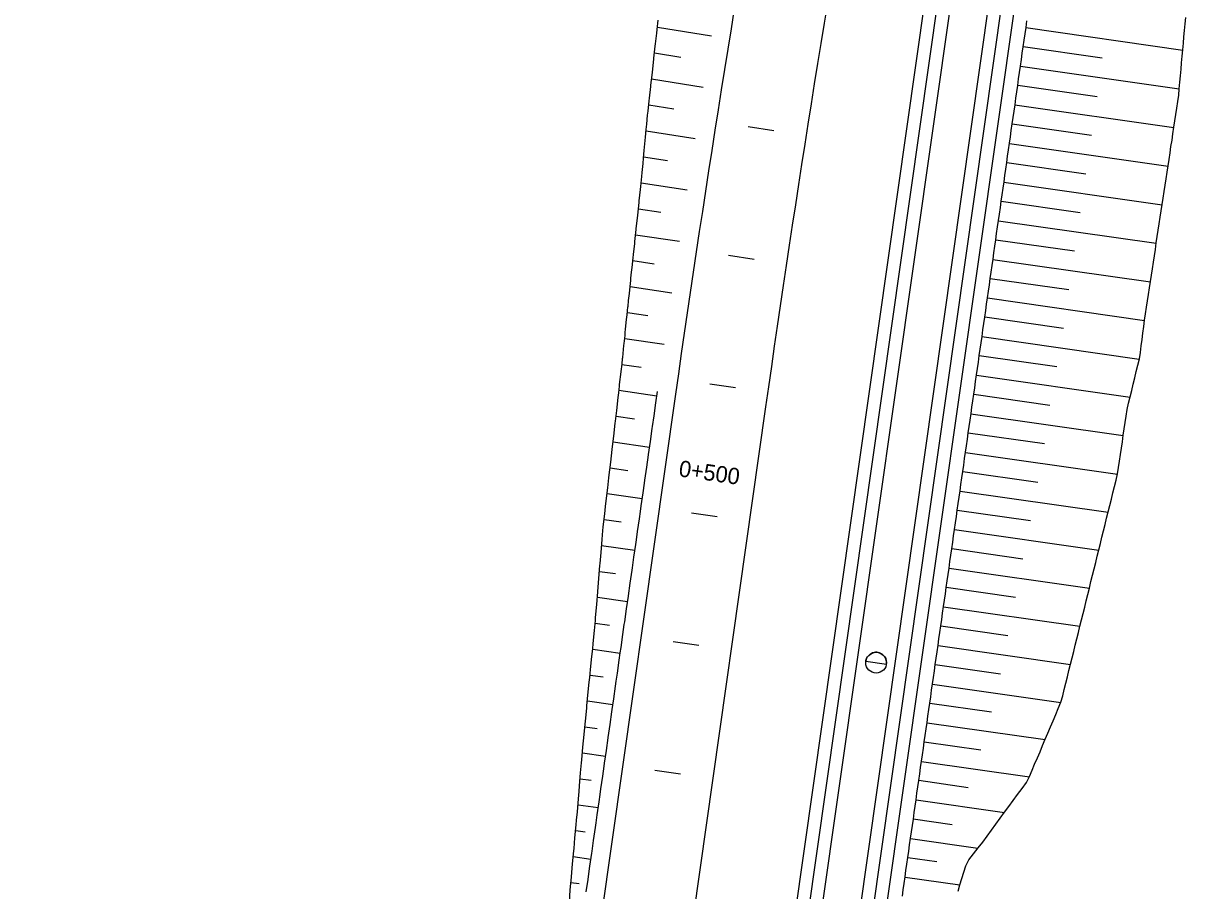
# Model space of a CAD drawing. Extents: x 6503541 to 6503743, y 5888004 to 5888145.
# Drawn here: x 6503703.334 to 6503705.481, y 5888126.143 to 5888127.745 of the extents above; entities that cross this region are included whole.
import ezdxf

# ---------------------------------------------------------------- set-up
doc = ezdxf.new("R2010")
doc.units = 0
doc.layers.add('12', color=7, linetype='Continuous')

msp = doc.modelspace()

# ---------------------------------------------------------------- linework, layer by layer
at = {"layer": '12'}
for p, q in [((6503703.334, 5888115.918), (6503705.1445, 5888128.6327)), ((6503703.8373, 5888119.6233), (6503705.1208, 5888128.6361)), ((6503703.3577, 5888115.9146), (6503705.1683, 5888128.6294)), ((6503703.4266, 5888115.9048), (6503705.2372, 5888128.6195)), ((6503703.4504, 5888115.9014), (6503705.2609, 5888128.6162)), ((6503704.0013, 5888119.5999), (6503705.2847, 5888128.6128)), ((6503705.1861, 5888127.7365), (6503705.4758, 5888127.6952)), ((6503705.3268, 5888127.6801), (6503705.181, 5888127.7008)), ((6503705.1759, 5888127.6652), (6503705.4693, 5888127.6234)), ((6503705.3178, 5888127.6086), (6503705.1709, 5888127.6295)), ((6503705.1658, 5888127.5939), (6503705.4594, 5888127.5521)), ((6503705.3073, 5888127.5374), (6503705.1607, 5888127.5582)), ((6503705.1556, 5888127.5226), (6503705.4486, 5888127.4809)), ((6503705.2969, 5888127.4661), (6503705.1506, 5888127.487)), ((6503705.1455, 5888127.4513), (6503705.4377, 5888127.4097)), ((6503705.2864, 5888127.3949), (6503705.1404, 5888127.4157)), ((6503705.1353, 5888127.38), (6503705.4269, 5888127.3385)), ((6503705.2759, 5888127.3237), (6503705.1303, 5888127.3444)), ((6503705.1252, 5888127.3088), (6503705.416, 5888127.2673)), ((6503705.2654, 5888127.2524), (6503705.1201, 5888127.2731)), ((6503705.115, 5888127.2375), (6503705.4053, 5888127.1962)), ((6503705.2553, 5888127.1811), (6503705.11, 5888127.2018)), ((6503705.1049, 5888127.1662), (6503705.3955, 5888127.1248)), ((6503705.2434, 5888127.1101), (6503705.0998, 5888127.1306)), ((6503705.0947, 5888127.0949), (6503705.3784, 5888127.0545)), ((6503704.5387, 5888127.06), (6503703.8027, 5888121.8909)), ((6503705.2304, 5888127.0392), (6503705.0897, 5888127.0593)), ((6503704.7051, 5888127.0363), (6503703.969, 5888121.8672)), ((6503705.0846, 5888127.0236), (6503705.3659, 5888126.9836)), ((6503705.2201, 5888126.968), (6503705.0795, 5888126.988)), ((6503705.0744, 5888126.9524), (6503705.3553, 5888126.9124)), ((6503705.208, 5888126.897), (6503705.0694, 5888126.9167)), ((6503705.0643, 5888126.8811), (6503705.338, 5888126.8421)), ((6503705.1943, 5888126.8262), (6503705.0592, 5888126.8454)), ((6503705.0541, 5888126.8098), (6503705.3206, 5888126.7719)), ((6503705.1805, 5888126.7554), (6503705.0491, 5888126.7742)), ((6503705.044, 5888126.7385), (6503705.3032, 5888126.7016)), ((6503705.1667, 5888126.6847), (6503705.0389, 5888126.7029)), ((6503705.0338, 5888126.6672), (6503705.2858, 5888126.6314)), ((6503705.1529, 5888126.6139), (6503705.0288, 5888126.6316)), ((6503705.0237, 5888126.596), (6503705.2684, 5888126.5611)), ((6503705.1391, 5888126.5432), (6503705.0186, 5888126.5603)), ((6503705.0135, 5888126.5247), (6503705.2506, 5888126.4909)), ((6503705.1223, 5888126.4728), (6503705.0085, 5888126.489)), ((6503705.0034, 5888126.4534), (6503705.2216, 5888126.4223)), ((6503705.1027, 5888126.4029), (6503704.9983, 5888126.4178)), ((6503704.9932, 5888126.3821), (6503705.1925, 5888126.3537)), ((6503705.0793, 5888126.3335), (6503704.9882, 5888126.3465)), ((6503704.9831, 5888126.3108), (6503705.1463, 5888126.2876)), ((6503705.0501, 5888126.2649), (6503704.978, 5888126.2752)), ((6503704.9729, 5888126.2396), (6503705.0974, 5888126.2218)), ((6503705.0213, 5888126.1963), (6503704.9679, 5888126.2039)), ((6503704.9628, 5888126.1683), (6503705.064, 5888126.1539))]:
    msp.add_line(p, q, dxfattribs=at)
for points in [[(6503704.3431, 5888126.1211), (6503704.3445, 5888126.1452), (6503704.3466, 5888126.1684), (6503704.3466, 5888126.1691), (6503704.3488, 5888126.193), (6503704.351, 5888126.217), (6503704.3513, 5888126.2211), (6503704.3531, 5888126.2409), (6503704.3553, 5888126.2648), (6503704.3561, 5888126.2737), (6503704.3575, 5888126.2888), (6503704.3597, 5888126.3127), (6503704.3609, 5888126.3264), (6503704.3616, 5888126.3367), (6503704.3633, 5888126.3607), (6503704.3651, 5888126.3791), (6503704.3656, 5888126.3846), (6503704.3679, 5888126.4085), (6503704.3702, 5888126.4317), (6503704.3702, 5888126.4324), (6503704.3725, 5888126.4563), (6503704.3748, 5888126.4802), (6503704.3752, 5888126.4843), (6503704.3771, 5888126.5042), (6503704.3795, 5888126.5281), (6503704.3804, 5888126.5369), (6503704.382, 5888126.5519), (6503704.3844, 5888126.5758), (6503704.3858, 5888126.5895), (6503704.3869, 5888126.5997), (6503704.3893, 5888126.6236), (6503704.3909, 5888126.6421), (6503704.3913, 5888126.6476), (6503704.3933, 5888126.6715), (6503704.3953, 5888126.6948), (6503704.3953, 5888126.6955), (6503704.3973, 5888126.7195), (6503704.3992, 5888126.7434), (6503704.3996, 5888126.7475), (6503704.4012, 5888126.7674), (6503704.4031, 5888126.7914), (6503704.4038, 5888126.8003), (6503704.4053, 5888126.8153), (6503704.4081, 5888126.8391), (6503704.4097, 5888126.8527), (6503704.4109, 5888126.863), (6503704.4137, 5888126.8868), (6503704.4158, 5888126.9052), (6503704.4164, 5888126.9107), (6503704.4192, 5888126.9345), (6503704.4219, 5888126.9577), (6503704.4219, 5888126.9584), (6503704.4247, 5888126.9822), (6503704.4274, 5888127.0061), (6503704.4279, 5888127.0102), (6503704.4302, 5888127.0299), (6503704.4329, 5888127.0538), (6503704.4339, 5888127.0626), (6503704.4353, 5888127.0747), (6503704.4356, 5888127.0777), (6503704.4384, 5888127.101), (6503704.4385, 5888127.1016), (6503704.44, 5888127.1153), (6503704.4411, 5888127.1256), (6503704.4412, 5888127.1273), (6503704.4435, 5888127.1496), (6503704.444, 5888127.1536), (6503704.4455, 5888127.1682), (6503704.446, 5888127.1737), (6503704.4467, 5888127.1799), (6503704.4485, 5888127.1977), (6503704.4494, 5888127.2062), (6503704.451, 5888127.221), (6503704.4511, 5888127.2217), (6503704.4522, 5888127.2326), (6503704.4536, 5888127.2457), (6503704.455, 5888127.2589), (6503704.4561, 5888127.2697), (6503704.4565, 5888127.2738), (6503704.4577, 5888127.2852), (6503704.4587, 5888127.2937), (6503704.4605, 5888127.3115), (6503704.4612, 5888127.3178), (6503704.4634, 5888127.3378), (6503704.4638, 5888127.3418), (6503704.4662, 5888127.3641), (6503704.4664, 5888127.3658), (6503704.469, 5888127.3898), (6503704.469, 5888127.3904), (6503704.4716, 5888127.4138), (6503704.4719, 5888127.4168), (6503704.4742, 5888127.4378), (6503704.4748, 5888127.4431), (6503704.4765, 5888127.4619), (6503704.4772, 5888127.4694), (6503704.4788, 5888127.486), (6503704.4797, 5888127.4958), (6503704.4811, 5888127.51), (6503704.4822, 5888127.5222), (6503704.4834, 5888127.5341), (6503704.4848, 5888127.5486), (6503704.4857, 5888127.5582), (6503704.4873, 5888127.5749), (6503704.488, 5888127.5822), (6503704.4901, 5888127.6013), (6503704.4907, 5888127.6063), (6503704.4931, 5888127.6276), (6503704.4934, 5888127.6303), (6503704.496, 5888127.6539), (6503704.4961, 5888127.6543), (6503704.4988, 5888127.6783), (6503704.499, 5888127.6802), (6503704.5015, 5888127.7023), (6503704.502, 5888127.7065), (6503704.5042, 5888127.7263), (6503704.505, 5888127.7328), (6503704.507, 5888127.7504)], [(6503705.0606, 5888126.1427), (6503705.0642, 5888126.1543), (6503705.0677, 5888126.1659), (6503705.0713, 5888126.1775), (6503705.0749, 5888126.1891), (6503705.0805, 5888126.2004), (6503705.0891, 5888126.2113), (6503705.0977, 5888126.2222), (6503705.1063, 5888126.2331), (6503705.1144, 5888126.2441), (6503705.1224, 5888126.2551), (6503705.1305, 5888126.266), (6503705.1386, 5888126.277), (6503705.1466, 5888126.288), (6503705.1547, 5888126.299), (6503705.1628, 5888126.3099), (6503705.1708, 5888126.3209), (6503705.1789, 5888126.3319), (6503705.187, 5888126.3429), (6503705.1927, 5888126.3542), (6503705.1974, 5888126.3656), (6503705.2021, 5888126.3771), (6503705.2072, 5888126.3885), (6503705.2121, 5888126.3999), (6503705.2169, 5888126.4113), (6503705.2217, 5888126.4228), (6503705.2266, 5888126.4342), (6503705.2314, 5888126.4456), (6503705.2363, 5888126.457), (6503705.2411, 5888126.4685), (6503705.2459, 5888126.4799), (6503705.2508, 5888126.4913), (6503705.254, 5888126.503), (6503705.2569, 5888126.5147), (6503705.2598, 5888126.5264), (6503705.2627, 5888126.5381), (6503705.2656, 5888126.5498), (6503705.2685, 5888126.5615), (6503705.2714, 5888126.5733), (6503705.2743, 5888126.585), (6503705.2772, 5888126.5967), (6503705.2801, 5888126.6084), (6503705.283, 5888126.6201), (6503705.2859, 5888126.6318), (6503705.2888, 5888126.6435), (6503705.2917, 5888126.6552), (6503705.2946, 5888126.6669), (6503705.2975, 5888126.6786), (6503705.3004, 5888126.6903), (6503705.3033, 5888126.702), (6503705.3062, 5888126.7138), (6503705.3091, 5888126.7255), (6503705.312, 5888126.7372), (6503705.3149, 5888126.7489), (6503705.3178, 5888126.7606), (6503705.3207, 5888126.7723), (6503705.3236, 5888126.784), (6503705.3265, 5888126.7957), (6503705.3294, 5888126.8074), (6503705.3323, 5888126.8191), (6503705.3352, 5888126.8308), (6503705.3381, 5888126.8425), (6503705.341, 5888126.8542), (6503705.3439, 5888126.866), (6503705.3468, 5888126.8777), (6503705.3497, 5888126.8894), (6503705.3526, 5888126.9011), (6503705.3554, 5888126.9128), (6503705.3572, 5888126.9247), (6503705.3589, 5888126.9365), (6503705.3607, 5888126.9484), (6503705.3624, 5888126.9603), (6503705.3642, 5888126.9722), (6503705.3659, 5888126.984), (6503705.3677, 5888126.9959), (6503705.3694, 5888127.0078), (6503705.3712, 5888127.0196), (6503705.3729, 5888127.0315), (6503705.3757, 5888127.0432), (6503705.3786, 5888127.055), (6503705.3814, 5888127.0667), (6503705.3842, 5888127.0784), (6503705.3871, 5888127.0901), (6503705.3899, 5888127.1018), (6503705.3927, 5888127.1135), (6503705.3956, 5888127.1253), (6503705.3977, 5888127.1371), (6503705.3992, 5888127.149), (6503705.4007, 5888127.1609), (6503705.4023, 5888127.1728), (6503705.4038, 5888127.1847), (6503705.4053, 5888127.1966), (6503705.4071, 5888127.2085), (6503705.4089, 5888127.2203), (6503705.4107, 5888127.2322), (6503705.4125, 5888127.2441), (6503705.4143, 5888127.2559), (6503705.4161, 5888127.2678), (6503705.4179, 5888127.2797), (6503705.4197, 5888127.2915), (6503705.4215, 5888127.3034), (6503705.4233, 5888127.3152), (6503705.4251, 5888127.3271), (6503705.4269, 5888127.339), (6503705.4287, 5888127.3508), (6503705.4306, 5888127.3627), (6503705.4324, 5888127.3746), (6503705.4342, 5888127.3864), (6503705.436, 5888127.3983), (6503705.4378, 5888127.4102), (6503705.4396, 5888127.422), (6503705.4414, 5888127.4339), (6503705.4432, 5888127.4457), (6503705.445, 5888127.4576), (6503705.4468, 5888127.4695), (6503705.4486, 5888127.4813), (6503705.4504, 5888127.4932), (6503705.4522, 5888127.5051), (6503705.454, 5888127.5169), (6503705.4559, 5888127.5288), (6503705.4577, 5888127.5407), (6503705.4595, 5888127.5525), (6503705.4613, 5888127.5644), (6503705.4631, 5888127.5762), (6503705.4649, 5888127.5881), (6503705.4667, 5888127.6), (6503705.4682, 5888127.6119), (6503705.4694, 5888127.6238), (6503705.4704, 5888127.6358), (6503705.4715, 5888127.6478), (6503705.4726, 5888127.6597), (6503705.4737, 5888127.6717), (6503705.4748, 5888127.6837), (6503705.4759, 5888127.6956), (6503705.4769, 5888127.7076), (6503705.478, 5888127.7196), (6503705.4791, 5888127.7315), (6503705.4802, 5888127.7435), (6503705.4813, 5888127.7555)], [(6503704.5055, 5888127.7376), (6503704.6052, 5888127.7215)], [(6503704.9578, 5888126.1331), (6503704.9595, 5888126.1449), (6503704.9612, 5888126.1568), (6503704.9628, 5888126.1687), (6503704.9645, 5888126.1806), (6503704.9662, 5888126.1925), (6503704.9679, 5888126.2044), (6503704.9696, 5888126.2162), (6503704.9713, 5888126.2281), (6503704.973, 5888126.24), (6503704.9747, 5888126.2519), (6503704.9764, 5888126.2638), (6503704.9781, 5888126.2756), (6503704.9798, 5888126.2875), (6503704.9815, 5888126.2994), (6503704.9831, 5888126.3113), (6503704.9848, 5888126.3232), (6503704.9865, 5888126.335), (6503704.9882, 5888126.3469), (6503704.9899, 5888126.3588), (6503704.9916, 5888126.3707), (6503704.9933, 5888126.3826), (6503704.995, 5888126.3944), (6503704.9967, 5888126.4063), (6503704.9984, 5888126.4182), (6503705.0001, 5888126.4301), (6503705.0018, 5888126.442), (6503705.0035, 5888126.4538), (6503705.0051, 5888126.4657), (6503705.0068, 5888126.4776), (6503705.0085, 5888126.4895), (6503705.0102, 5888126.5014), (6503705.0119, 5888126.5132), (6503705.0136, 5888126.5251), (6503705.0153, 5888126.537), (6503705.017, 5888126.5489), (6503705.0187, 5888126.5608), (6503705.0204, 5888126.5726), (6503705.0221, 5888126.5845), (6503705.0238, 5888126.5964), (6503705.0254, 5888126.6083), (6503705.0271, 5888126.6202), (6503705.0288, 5888126.632), (6503705.0305, 5888126.6439), (6503705.0322, 5888126.6558), (6503705.0339, 5888126.6677), (6503705.0356, 5888126.6796), (6503705.0373, 5888126.6914), (6503705.039, 5888126.7033), (6503705.0407, 5888126.7152), (6503705.0424, 5888126.7271), (6503705.0441, 5888126.739), (6503705.0457, 5888126.7508), (6503705.0474, 5888126.7627), (6503705.0491, 5888126.7746), (6503705.0508, 5888126.7865), (6503705.0525, 5888126.7984), (6503705.0542, 5888126.8102), (6503705.0559, 5888126.8221), (6503705.0576, 5888126.834), (6503705.0593, 5888126.8459), (6503705.061, 5888126.8578), (6503705.0627, 5888126.8696), (6503705.0644, 5888126.8815), (6503705.066, 5888126.8934), (6503705.0677, 5888126.9053), (6503705.0694, 5888126.9172), (6503705.0711, 5888126.929), (6503705.0728, 5888126.9409), (6503705.0745, 5888126.9528), (6503705.0762, 5888126.9647), (6503705.0779, 5888126.9766), (6503705.0796, 5888126.9884), (6503705.0813, 5888127.0003), (6503705.083, 5888127.0122), (6503705.0847, 5888127.0241), (6503705.0863, 5888127.036), (6503705.088, 5888127.0478), (6503705.0897, 5888127.0597), (6503705.0914, 5888127.0716), (6503705.0931, 5888127.0835), (6503705.0948, 5888127.0954), (6503705.0965, 5888127.1072), (6503705.0982, 5888127.1191), (6503705.0999, 5888127.131), (6503705.1016, 5888127.1429), (6503705.1033, 5888127.1548), (6503705.105, 5888127.1666), (6503705.1066, 5888127.1785), (6503705.1083, 5888127.1904), (6503705.11, 5888127.2023), (6503705.1117, 5888127.2142), (6503705.1134, 5888127.226), (6503705.1151, 5888127.2379), (6503705.1168, 5888127.2498), (6503705.1185, 5888127.2617), (6503705.1202, 5888127.2736), (6503705.1219, 5888127.2854), (6503705.1236, 5888127.2973), (6503705.1253, 5888127.3092), (6503705.1269, 5888127.3211), (6503705.1286, 5888127.333), (6503705.1303, 5888127.3448), (6503705.132, 5888127.3567), (6503705.1337, 5888127.3686), (6503705.1354, 5888127.3805), (6503705.1371, 5888127.3924), (6503705.1388, 5888127.4042), (6503705.1405, 5888127.4161), (6503705.1422, 5888127.428), (6503705.1439, 5888127.4399), (6503705.1456, 5888127.4518), (6503705.1472, 5888127.4636), (6503705.1489, 5888127.4755), (6503705.1506, 5888127.4874), (6503705.1523, 5888127.4993), (6503705.154, 5888127.5112), (6503705.1557, 5888127.523), (6503705.1574, 5888127.5349), (6503705.1591, 5888127.5468), (6503705.1608, 5888127.5587), (6503705.1625, 5888127.5706), (6503705.1642, 5888127.5824), (6503705.1659, 5888127.5943), (6503705.1675, 5888127.6062), (6503705.1692, 5888127.6181), (6503705.1709, 5888127.63), (6503705.1726, 5888127.6418), (6503705.1743, 5888127.6537), (6503705.176, 5888127.6656), (6503705.1777, 5888127.6775), (6503705.1794, 5888127.6894), (6503705.1811, 5888127.7013), (6503705.1828, 5888127.7131), (6503705.1845, 5888127.725), (6503705.1862, 5888127.7369), (6503705.1878, 5888127.7488)], [(6503704.5001, 5888127.6897), (6503704.5488, 5888127.6819)], [(6503704.4947, 5888127.6418), (6503704.59, 5888127.6267)], [(6503704.4893, 5888127.594), (6503704.5359, 5888127.5866)], [(6503704.4845, 5888127.546), (6503704.5751, 5888127.5319)], [(6503704.7206, 5888127.5458), (6503704.6732, 5888127.5532)], [(6503704.4799, 5888127.498), (6503704.5239, 5888127.4912)], [(6503704.4754, 5888127.45), (6503704.5605, 5888127.437)], [(6503704.4703, 5888127.4021), (6503704.5118, 5888127.3958)], [(6503704.4651, 5888127.3543), (6503704.5461, 5888127.3421)], [(6503704.46, 5888127.3064), (6503704.4995, 5888127.3005)], [(6503704.6843, 5888127.3087), (6503704.6368, 5888127.3158)], [(6503704.4549, 5888127.2585), (6503704.5319, 5888127.2471)], [(6503704.4499, 5888127.2106), (6503704.4874, 5888127.2051)], [(6503704.4449, 5888127.1628), (6503704.518, 5888127.1522)], [(6503704.4399, 5888127.1149), (6503704.4756, 5888127.1098)], [(6503704.3739, 5888126.141), (6503704.3772, 5888126.1641), (6503704.3773, 5888126.1647), (6503704.3807, 5888126.1885), (6503704.3841, 5888126.2123), (6503704.3847, 5888126.2163), (6503704.3875, 5888126.236), (6503704.3909, 5888126.2598), (6503704.3921, 5888126.2686), (6503704.3942, 5888126.2835), (6503704.3976, 5888126.3073), (6503704.3996, 5888126.3209), (6503704.401, 5888126.3311), (6503704.4044, 5888126.3548), (6503704.407, 5888126.3731), (6503704.4078, 5888126.3786), (6503704.4112, 5888126.4023), (6503704.4144, 5888126.4254), (6503704.4145, 5888126.4261), (6503704.4179, 5888126.4499), (6503704.4213, 5888126.4736), (6503704.4219, 5888126.4777), (6503704.4247, 5888126.4974), (6503704.4281, 5888126.5211), (6503704.4293, 5888126.53), (6503704.4315, 5888126.5449), (6503704.4348, 5888126.5687), (6503704.4368, 5888126.5822), (6503704.4382, 5888126.5924), (6503704.4416, 5888126.6162), (6503704.4442, 5888126.6345), (6503704.445, 5888126.6399), (6503704.4484, 5888126.6637), (6503704.4517, 5888126.6868), (6503704.4518, 5888126.6875), (6503704.4551, 5888126.7112), (6503704.4585, 5888126.735), (6503704.4591, 5888126.7391), (6503704.4619, 5888126.7587), (6503704.4653, 5888126.7825), (6503704.4665, 5888126.7913), (6503704.4687, 5888126.8063), (6503704.4721, 5888126.83), (6503704.474, 5888126.8436), (6503704.4754, 5888126.8538), (6503704.4788, 5888126.8775), (6503704.4814, 5888126.8959), (6503704.4822, 5888126.9013), (6503704.4856, 5888126.9251), (6503704.4889, 5888126.9481), (6503704.489, 5888126.9488), (6503704.4924, 5888126.9726), (6503704.4957, 5888126.9963), (6503704.4963, 5888127.0004), (6503704.4991, 5888127.0201), (6503704.5025, 5888127.0439), (6503704.5055, 5888127.0647)], [(6503704.4344, 5888127.0671), (6503704.5044, 5888127.0571)], [(6503704.6495, 5888127.0714), (6503704.602, 5888127.0782)], [(6503704.4289, 5888127.0194), (6503704.4633, 5888127.0145)], [(6503704.4235, 5888126.9717), (6503704.4909, 5888126.9621)], [(6503704.418, 5888126.924), (6503704.451, 5888126.9193)], [(6503704.4125, 5888126.8763), (6503704.4773, 5888126.867)], [(6503704.4069, 5888126.8286), (6503704.4387, 5888126.8241)], [(6503704.5681, 5888126.8406), (6503704.6156, 5888126.8338)], [(6503704.4022, 5888126.7808), (6503704.4638, 5888126.772)], [(6503704.3984, 5888126.7328), (6503704.4277, 5888126.7287)], [(6503704.3944, 5888126.6849), (6503704.4503, 5888126.677)], [(6503704.3905, 5888126.637), (6503704.417, 5888126.6332)], [(6503704.5818, 5888126.5962), (6503704.5343, 5888126.603)], [(6503704.3858, 5888126.5892), (6503704.4367, 5888126.5819)], [(6503704.8903, 5888126.5669), (6503704.9284, 5888126.5615)], [(6503704.3809, 5888126.5414), (6503704.4054, 5888126.5379)], [(6503704.3761, 5888126.4936), (6503704.4232, 5888126.4869)], [(6503704.3715, 5888126.4458), (6503704.394, 5888126.4426)], [(6503704.3669, 5888126.3979), (6503704.4097, 5888126.3918)], [(6503704.548, 5888126.3586), (6503704.5004, 5888126.3654)], [(6503704.3626, 5888126.3501), (6503704.3827, 5888126.3472)], [(6503704.3587, 5888126.3021), (6503704.3961, 5888126.2968)], [(6503704.3544, 5888126.2543), (6503704.3719, 5888126.2518)], [(6503704.35, 5888126.2064), (6503704.3826, 5888126.2018)], [(6503704.3457, 5888126.1585), (6503704.3608, 5888126.1564)]]:
    msp.add_lwpolyline(points, dxfattribs=at)
msp.add_circle((6503704.9094, 5888126.5642), 0.0192, dxfattribs=at)
for centre, radius, start, end in [((6503740.2624, 5888121.973), 36.084, 168.04536, 171.89568), ((6503740.2624, 5888121.973), 35.916, 168.04536, 171.89568), ((6503704.9094, 5888126.5642), 0.0192, 47.4484, 171.8957), ((6503704.9094, 5888126.5642), 0.0192, 351.8957, 47.4484)]:
    msp.add_arc(centre, radius, start, end, dxfattribs=at)

# ---------------------------------------------------------------- texts
msp.add_text('0+500', height=0.03, rotation=351.8957, dxfattribs=at).set_placement((6503704.5436, 5888126.9084))

doc.saveas('drawing.dxf')
